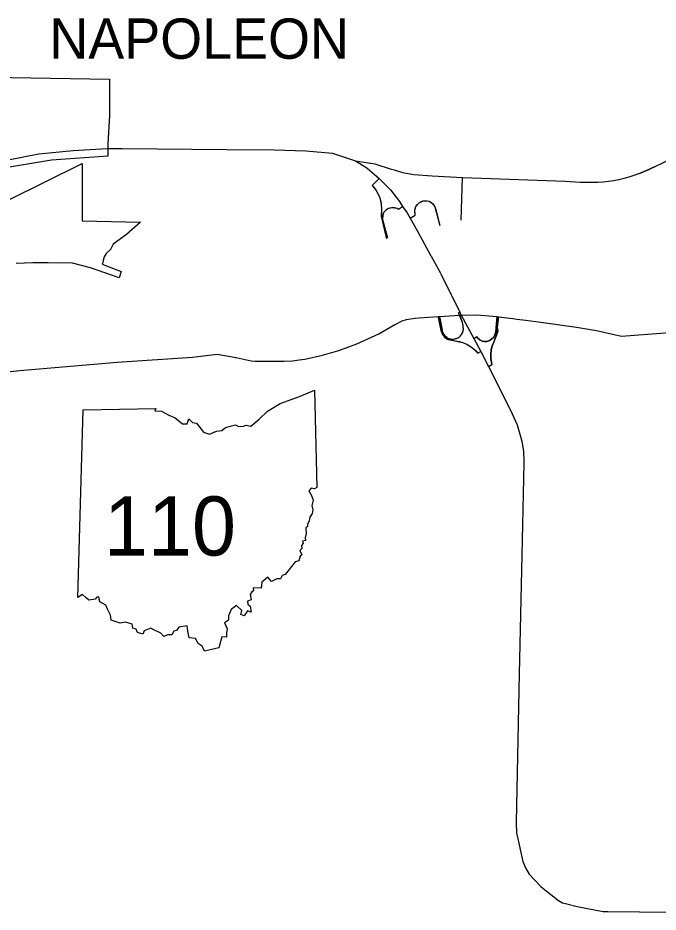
# Model space of a CAD drawing. Extents: x -62 to 810, y 0 to 440.
# Drawn here: x 317.5 to 358.3, y 263.1 to 320 of the extents above; entities that cross this region are included whole.
import ezdxf

# ---------------------------------------------------------------- set-up
doc = ezdxf.new("R2010")
doc.units = 0
for name, color, linetype in [('Default', 7, 'Continuous'), ('DV_X_Corp_Line', 7, 'Continuous'), ('GM_X_Corporation_Text', 7, 'Continuous'), ('GM_X_State_Route', 7, 'Continuous'), ('PV_P_Text', 7, 'Continuous')]:
    doc.layers.add(name, color=color, linetype=linetype)

msp = doc.modelspace()

# ---------------------------------------------------------------- linework, layer by layer
at = {"layer": 'Default'}
for points in [[(340.502, 309.768), (340.066, 309.315), (340.322, 309.016), (340.549, 308.539), (340.642, 308.115), (340.651, 307.842), (340.641, 307.378), (340.67, 307.189), (340.974, 305.947)], [(342.473, 307.243), (342.811, 307.435), (342.776, 307.723), (342.843, 307.987), (343.056, 308.233), (343.309, 308.347), (343.696, 308.321), (343.9, 308.19), (344.061, 307.968), (344.375, 306.786)], [(341.063, 305.969), (340.745, 307.141), (340.765, 307.487), (340.83, 307.64), (341.067, 307.859), (341.324, 307.931), (341.65, 307.885), (341.741, 307.825), (342.005, 307.999)], [(344.261, 300.988), (344.448, 300.081), (344.603, 299.756), (344.665, 299.675), (344.865, 299.552), (345.06, 299.499), (345.434, 299.429), (345.807, 299.341), (346.135, 299.204), (346.474, 298.977), (346.784, 298.661), (346.986, 298.77)], [(344.347, 300.994), (344.55, 299.987), (344.629, 299.84), (344.881, 299.617), (345.103, 299.552), (345.245, 299.556), (345.578, 299.652), (345.771, 299.864), (345.857, 300.096), (345.873, 300.171), (345.847, 300.43), (345.813, 300.607), (345.634, 301.069)], [(346.539, 299.597), (346.716, 299.693), (346.913, 299.5), (347.07, 299.426), (347.21, 299.393), (347.37, 299.406), (347.526, 299.467), (347.8, 299.672), (347.876, 299.817), (347.937, 300.007), (348.013, 300.994)], [(348.108, 300.981), (348.025, 300.289), (348.055, 300.069), (347.978, 299.812), (347.725, 299.172), (347.643, 298.903), (347.61, 298.601), (347.607, 298.338), (347.677, 297.924), (347.468, 297.819)]]:
    msp.add_lwpolyline(points, dxfattribs=at)
at = {"layer": 'DV_X_Corp_Line'}
for points in [[(315.819, 316.215), (323.348, 316.084), (323.348, 313.781), (323.238, 311.985), (323.239, 311.186), (319.649, 310.928), (316.991, 310.49)], [(316.904, 308.389), (321.615, 310.726), (321.602, 307.084), (325.327, 306.987), (324.419, 306.2), (323.584, 305.592), (323.419, 305.263), (323.142, 305.006), (323.004, 304.782), (322.947, 304.548), (322.916, 304.424), (322.889, 304.313), (324.086, 303.853), (323.957, 303.449), (322.147, 304.08), (320.994, 304.387), (319.451, 304.407), (318.46, 304.406), (317.398, 304.357)]]:
    msp.add_lwpolyline(points, dxfattribs=at)
at = {"layer": 'GM_X_State_Route'}
for p, q in [((358.077, 310.544), (367.562, 315)), ((352.351, 309.6), (353.315, 309.546))]:
    msp.add_line(p, q, dxfattribs=at)
for points in [[(306.783, 308.874), (308.116, 309.154), (311.114, 309.784), (311.937, 309.956), (315.684, 310.733), (318.857, 311.332), (321.027, 311.554), (323.207, 311.679), (323.382, 311.678)], [(323.382, 311.678), (324.145, 311.672)], [(324.145, 311.672), (330.815, 311.619), (333.831, 311.594), (335.838, 311.527), (337.541, 311.372), (339.013, 310.893)], [(339.013, 310.893), (339.732, 310.44), (340.502, 309.768), (341.239, 309.059), (341.795, 308.316), (342.005, 307.999), (342.283, 307.58), (342.473, 307.243), (342.944, 306.426)], [(339.013, 310.893), (340.225, 310.703), (341.265, 310.372), (341.456, 310.315), (341.461, 310.314)], [(341.461, 310.314), (342.004, 310.153), (342.721, 310.02), (343.889, 309.938), (345.803, 309.841)], [(340.502, 309.768), (340.066, 309.315), (340.147, 309.234), (340.322, 309.016), (340.456, 308.775), (340.549, 308.539), (340.618, 308.305), (340.642, 308.115), (340.651, 307.842), (340.651, 307.565), (340.641, 307.378), (340.67, 307.189), (340.936, 306.105), (340.974, 305.947)], [(345.719, 307.124), (345.803, 309.841)], [(345.803, 309.841), (352.351, 309.6), (352.364, 309.6)], [(342.473, 307.243), (342.811, 307.435), (342.792, 307.515), (342.776, 307.723), (342.803, 307.858), (342.843, 307.987), (342.94, 308.117), (343.056, 308.233), (343.187, 308.306), (343.309, 308.347), (343.45, 308.36), (343.565, 308.35), (343.696, 308.321), (343.804, 308.26), (343.9, 308.19), (343.991, 308.09), (344.061, 307.968), (344.119, 307.793), (344.335, 306.944), (344.375, 306.786)], [(341.063, 305.969), (341.024, 306.129), (340.905, 306.501), (340.745, 307.141), (340.731, 307.326), (340.765, 307.487), (340.83, 307.64), (340.951, 307.772), (341.067, 307.859), (341.186, 307.909), (341.324, 307.931), (341.483, 307.935), (341.65, 307.885), (341.741, 307.825), (342.005, 307.999)], [(342.944, 306.426), (343.804, 304.854)], [(343.804, 304.854), (343.812, 304.84), (344.39, 303.783), (344.445, 303.673), (345.111, 302.336)], [(345.111, 302.336), (345.129, 302.299), (345.644, 301.266), (345.734, 301.084)], [(342.776, 300.89), (342.795, 300.893), (343.034, 300.909), (344.261, 300.988), (344.347, 300.994), (345.625, 301.077), (345.734, 301.084), (346.709, 301.102), (348.013, 300.994), (348.108, 300.981), (349.006, 300.861)], [(344.261, 300.988), (344.263, 300.952), (344.444, 300.091), (344.494, 299.959), (344.603, 299.756), (344.665, 299.675), (344.865, 299.552), (345.116, 299.476), (345.434, 299.429), (345.619, 299.394), (345.807, 299.341), (345.982, 299.275), (346.279, 299.115), (346.474, 298.977), (346.634, 298.833), (346.784, 298.661), (346.986, 298.77)], [(344.261, 300.988), (344.263, 300.952), (344.303, 300.769), (344.448, 300.081), (344.494, 299.959), (344.547, 299.848), (344.603, 299.756), (344.665, 299.675), (344.76, 299.604), (344.865, 299.552), (344.98, 299.505), (345.116, 299.476), (345.619, 299.394), (345.807, 299.341), (345.982, 299.275), (346.135, 299.204), (346.279, 299.115), (346.474, 298.977), (346.634, 298.833), (346.761, 298.69), (346.784, 298.661), (346.986, 298.77)], [(344.347, 300.994), (344.511, 300.128), (344.55, 299.987), (344.629, 299.84), (344.734, 299.729), (344.881, 299.617), (345.103, 299.552), (345.245, 299.556), (345.421, 299.591), (345.578, 299.652), (345.666, 299.731), (345.771, 299.864), (345.833, 300.001), (345.873, 300.171), (345.863, 300.351), (345.813, 300.607), (345.565, 301.227), (345.644, 301.266)], [(345.734, 301.084), (346.539, 299.597), (346.986, 298.77), (347.468, 297.819), (348.808, 295.162), (348.831, 295.114)], [(346.539, 299.597), (346.716, 299.693), (346.769, 299.626), (346.913, 299.5), (347.07, 299.426), (347.21, 299.393), (347.37, 299.406), (347.526, 299.467), (347.666, 299.551), (347.8, 299.672), (347.876, 299.817), (347.937, 300.007), (348.013, 300.994)], [(348.013, 300.994), (348.005, 300.901), (347.937, 300.007), (347.876, 299.817), (347.8, 299.672), (347.666, 299.551), (347.526, 299.467), (347.37, 299.406), (347.21, 299.393), (347.07, 299.426), (346.913, 299.5), (346.769, 299.626), (346.716, 299.693), (346.539, 299.597)], [(348.108, 300.981), (348.025, 300.289), (348.012, 300.011), (347.978, 299.812), (347.918, 299.654), (347.725, 299.172), (347.643, 298.903), (347.61, 298.601), (347.607, 298.338), (347.677, 297.924), (347.468, 297.819)], [(347.468, 297.819), (347.677, 297.924), (347.671, 297.948), (347.607, 298.338), (347.61, 298.601), (347.643, 298.903), (347.725, 299.172), (347.82, 299.399), (347.918, 299.654), (347.978, 299.812), (348.012, 300.011), (348.025, 300.289), (348.098, 300.905), (348.108, 300.981)], [(335.409, 298.226), (335.597, 298.253), (335.776, 298.278), (336.901, 298.539), (337.936, 298.836), (339.082, 299.245), (340.491, 299.881), (341.517, 300.474)], [(341.517, 300.474), (341.569, 300.503), (341.98, 300.715), (342.256, 300.81), (342.776, 300.89)], [(349.006, 300.861), (349.031, 300.858), (349.263, 300.827), (349.471, 300.799), (349.847, 300.749), (350.801, 300.622)], [(350.801, 300.622), (353.067, 300.321), (354.335, 300.101), (355.937, 299.736), (360.668, 300.11)], [(315.23, 297.3), (317.647, 297.549), (323.83, 298.091), (328.623, 298.4), (330.189, 298.592)], [(330.189, 298.592), (331.272, 298.404)], [(331.272, 298.404), (331.374, 298.386), (331.418, 298.377), (332.356, 298.171), (332.614, 298.144), (333.216, 298.142), (334.454, 298.143), (335.003, 298.168), (335.409, 298.226)], [(348.831, 295.114), (348.97, 294.809), (349.294, 294.103), (349.591, 293.06), (349.68, 292.537)], [(349.68, 292.537), (349.699, 292.423), (349.704, 292.236)], [(349.704, 292.236), (349.704, 292.229), (349.712, 291.93), (349.719, 291.662), (349.592, 285.815), (349.427, 278.255), (349.222, 268.818), (349.255, 268.12), (349.286, 267.951), (349.649, 266.313), (349.818, 265.91), (350.052, 265.52), (350.807, 264.728), (350.937, 264.611), (351.93, 263.841), (352.172, 263.701), (352.446, 263.623), (353.113, 263.466), (354.77, 263.141), (355.008, 263.139)], [(355.008, 263.139), (355.055, 263.138), (359.098, 263.103)]]:
    msp.add_lwpolyline(points, dxfattribs=at)
msp.add_arc((354.092, 317.7), 8.165, 272.4693, 291.2067, dxfattribs=at)
for points in [[(357.045, 310.088), (357.06, 310.093), (357.074, 310.099), (357.088, 310.104), (357.102, 310.11), (357.116, 310.116), (357.131, 310.121), (357.145, 310.127), (357.159, 310.133), (357.173, 310.138), (357.187, 310.144), (357.201, 310.15), (357.215, 310.156), (357.229, 310.162), (357.244, 310.167), (357.258, 310.173), (357.272, 310.179), (357.286, 310.185), (357.3, 310.191), (357.314, 310.197), (357.328, 310.203), (357.342, 310.209), (357.356, 310.215), (357.37, 310.221), (357.384, 310.227), (357.398, 310.233), (357.412, 310.239), (357.426, 310.245), (357.44, 310.251), (357.454, 310.257), (357.468, 310.264), (357.482, 310.27), (357.496, 310.276), (357.51, 310.282), (357.524, 310.288), (357.538, 310.294), (357.551, 310.301), (357.565, 310.307), (357.579, 310.313), (357.593, 310.319), (357.607, 310.326), (357.621, 310.332), (357.635, 310.338), (357.649, 310.345), (357.663, 310.351), (357.677, 310.357), (357.69, 310.364), (357.704, 310.37), (357.718, 310.376), (357.732, 310.383), (357.746, 310.389), (357.76, 310.396), (357.774, 310.402), (357.787, 310.408), (357.801, 310.415), (357.815, 310.421), (357.829, 310.428), (357.843, 310.434), (357.857, 310.44), (357.87, 310.447), (357.884, 310.453), (357.898, 310.46), (357.912, 310.466), (357.926, 310.473), (357.939, 310.479), (357.953, 310.486), (357.967, 310.492), (357.981, 310.499), (357.995, 310.505), (358.008, 310.512), (358.022, 310.518), (358.036, 310.525), (358.05, 310.531), (358.064, 310.537), (358.077, 310.544)], [(353.315, 309.546), (353.331, 309.545), (353.346, 309.545), (353.361, 309.545), (353.376, 309.544), (353.392, 309.544), (353.407, 309.543), (353.422, 309.543), (353.437, 309.543), (353.453, 309.542), (353.468, 309.542), (353.483, 309.542), (353.498, 309.541), (353.514, 309.541), (353.529, 309.54), (353.544, 309.54), (353.559, 309.54), (353.575, 309.539), (353.59, 309.539), (353.605, 309.539), (353.62, 309.538), (353.636, 309.538), (353.651, 309.538), (353.666, 309.537), (353.681, 309.537), (353.697, 309.537), (353.712, 309.537), (353.727, 309.536), (353.742, 309.536), (353.758, 309.536), (353.773, 309.536), (353.788, 309.535), (353.803, 309.535), (353.819, 309.535), (353.834, 309.535), (353.849, 309.535), (353.864, 309.535), (353.88, 309.534), (353.895, 309.534), (353.91, 309.534), (353.925, 309.534), (353.941, 309.534), (353.956, 309.534), (353.971, 309.534), (353.986, 309.534), (354.002, 309.534), (354.017, 309.534), (354.032, 309.534), (354.047, 309.534), (354.063, 309.534), (354.078, 309.534), (354.093, 309.534), (354.108, 309.534), (354.124, 309.534), (354.139, 309.535), (354.154, 309.535), (354.169, 309.535), (354.185, 309.535), (354.2, 309.535), (354.215, 309.536), (354.23, 309.536), (354.246, 309.536), (354.261, 309.537), (354.276, 309.537), (354.291, 309.537), (354.307, 309.538), (354.322, 309.538), (354.337, 309.539), (354.352, 309.539), (354.368, 309.54), (354.383, 309.54), (354.398, 309.541), (354.413, 309.541), (354.429, 309.542), (354.444, 309.542)]]:
    msp.add_spline(points, degree=3, dxfattribs=at)
at = {"layer": 'PV_P_Text'}
msp.add_line((321.331, 283.124), (321.665, 295.06), dxfattribs=at)
msp.add_line((321.331, 283.124), (321.665, 295.06), dxfattribs=at)
for points in [[(321.665, 295.06), (326.296, 295.138), (326.224, 294.994), (326.661, 294.963), (327.125, 294.708), (327.517, 294.547), (327.998, 294.168), (328.285, 294.172), (328.407, 294.483), (328.627, 294.243), (328.888, 294.2), (329.339, 293.629), (329.712, 293.505), (330.158, 293.701), (330.492, 293.733), (330.736, 293.927), (331.371, 294.092), (331.549, 293.993), (331.885, 294.013), (332.054, 294.086), (332.348, 294.021), (332.864, 294.455), (333.396, 294.967), (334.214, 295.45), (335.436, 295.907), (336.402, 296.316), (336.541, 290.122)], [(321.665, 295.06), (326.296, 295.138), (326.224, 294.994), (326.661, 294.963), (327.125, 294.708), (327.517, 294.547), (327.998, 294.168), (328.285, 294.172), (328.407, 294.483), (328.627, 294.243), (328.888, 294.2), (329.339, 293.629), (329.712, 293.505), (330.158, 293.701), (330.492, 293.733), (330.736, 293.927), (331.371, 294.092), (331.549, 293.993), (331.885, 294.013), (332.054, 294.086), (332.348, 294.021), (332.864, 294.455), (333.396, 294.967), (334.214, 295.45), (335.436, 295.907), (336.402, 296.316), (336.541, 290.122)], [(336.541, 290.122), (336.399, 290.035), (336.177, 290.076), (336.028, 289.902), (336.212, 289.612), (336.299, 289.306), (336.222, 288.968), (336.298, 288.69), (336.247, 288.457), (336.107, 288.225), (336.059, 288.004), (335.94, 287.771), (335.95, 287.641), (335.837, 287.538), (335.858, 287.15), (335.8, 286.935), (335.82, 286.75), (335.637, 286.702), (335.679, 286.549), (335.562, 286.431), (335.587, 286.227), (335.455, 286.097), (335.583, 285.838), (335.48, 285.755), (335.395, 285.439), (335.159, 285.375), (334.688, 284.797), (334.522, 284.578), (334.335, 284.524), (334.232, 284.299), (334.003, 284.299), (333.655, 284.143), (333.43, 284.411), (333.036, 284.089), (332.99, 283.716), (332.492, 283.728), (332.512, 283.54), (332.4, 283.485), (332.299, 283.297), (332.358, 282.962), (332.125, 282.876), (332.153, 282.682), (332.302, 282.563), (332.369, 282.191), (332.121, 282.267), (331.918, 281.953), (331.709, 282.027), (331.777, 282.292), (331.425, 282.611), (331.091, 282.356), (330.917, 281.947), (330.915, 281.673), (330.666, 281.506), (330.826, 281.118), (330.796, 280.851), (330.801, 280.597), (330.49, 280.606), (330.302, 279.921)], [(336.541, 290.122), (336.399, 290.035), (336.177, 290.076), (336.028, 289.902), (336.212, 289.612), (336.299, 289.306), (336.222, 288.968), (336.298, 288.69), (336.247, 288.457), (336.107, 288.225), (336.059, 288.004), (335.94, 287.771), (335.95, 287.641), (335.837, 287.538), (335.858, 287.15), (335.8, 286.935), (335.82, 286.75), (335.637, 286.702), (335.679, 286.549), (335.562, 286.431), (335.587, 286.227), (335.455, 286.097), (335.583, 285.838), (335.48, 285.755), (335.395, 285.439), (335.159, 285.375), (334.688, 284.797), (334.522, 284.578), (334.335, 284.524), (334.232, 284.299), (334.003, 284.299), (333.655, 284.143), (333.43, 284.411), (333.036, 284.089), (332.99, 283.716), (332.492, 283.728), (332.512, 283.54), (332.4, 283.485), (332.299, 283.297), (332.358, 282.962), (332.125, 282.876), (332.153, 282.682), (332.302, 282.563), (332.369, 282.191), (332.121, 282.267), (331.918, 281.953), (331.709, 282.027), (331.777, 282.292), (331.425, 282.611), (331.091, 282.356), (330.917, 281.947), (330.915, 281.673), (330.666, 281.506), (330.826, 281.118), (330.796, 280.851), (330.801, 280.597), (330.49, 280.606), (330.302, 279.921)], [(330.302, 279.921), (329.762, 279.79), (329.386, 279.711), (329.254, 280.023), (328.986, 280.187), (328.811, 280.5), (328.426, 280.543), (328.335, 280.973), (328.292, 281.323), (327.765, 281.236), (327.62, 281.023), (327.434, 280.965), (327.325, 280.75), (327.07, 280.732), (326.797, 280.631), (326.618, 280.842), (326.171, 281.054), (325.969, 281.163), (325.548, 280.993), (325.459, 280.792), (325.124, 280.881), (325.045, 281.105), (324.842, 281.172), (324.798, 281.41), (324.364, 281.537), (324.033, 281.486), (323.448, 281.678), (323.413, 281.99), (323.213, 282.371), (323.11, 282.636), (322.74, 282.838), (322.665, 283.153), (322.547, 283.144), (322.439, 283.016), (322.028, 282.957), (321.864, 283.086), (321.634, 283.305), (321.331, 283.124)], [(330.302, 279.921), (329.762, 279.79), (329.386, 279.711), (329.254, 280.023), (328.986, 280.187), (328.811, 280.5), (328.426, 280.543), (328.335, 280.973), (328.292, 281.323), (327.765, 281.236), (327.62, 281.023), (327.434, 280.965), (327.325, 280.75), (327.07, 280.732), (326.797, 280.631), (326.618, 280.842), (326.171, 281.054), (325.969, 281.163), (325.548, 280.993), (325.459, 280.792), (325.124, 280.881), (325.045, 281.105), (324.842, 281.172), (324.798, 281.41), (324.364, 281.537), (324.033, 281.486), (323.448, 281.678), (323.413, 281.99), (323.213, 282.371), (323.11, 282.636), (322.74, 282.838), (322.665, 283.153), (322.547, 283.144), (322.439, 283.016), (322.028, 282.957), (321.864, 283.086), (321.634, 283.305), (321.331, 283.124)]]:
    msp.add_lwpolyline(points, dxfattribs=at)

# ---------------------------------------------------------------- texts
at = {"layer": 'GM_X_Corporation_Text'}
msp.add_text('NAPOLEON', height=2.565, rotation=0, dxfattribs=at).set_placement((319.522, 317.385))
at = {"layer": 'PV_P_Text'}
msp.add_text('110', height=3.7631, dxfattribs=at).set_placement((323, 285.786))

doc.saveas('drawing.dxf')
